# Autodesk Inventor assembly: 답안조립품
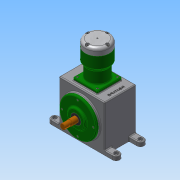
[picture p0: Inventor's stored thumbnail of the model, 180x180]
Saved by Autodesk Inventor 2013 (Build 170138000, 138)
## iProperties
Created: 2016-11
Part Number: 답안조립품
Document SubType Name: Assembly
Designer: Administrator
Author: Administrator
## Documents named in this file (16)
- C:\Users\Administrator\Desktop\361108V1018\답안조립품.iam
- C:\Users\Administrator\Desktop\361108V1018\본체.ipt
- C:\Users\Administrator\Desktop\361108V1018\메인크랭크축.ipt
- C:\Users\Administrator\Desktop\361108V1018\베어링 20 x 47 x 14.ipt
- C:\Users\Administrator\Desktop\361108V1018\베어링 NA 4902.ipt
- C:\Users\Administrator\Desktop\361108V1018\볼트 M4 x 8.ipt
- C:\Users\Administrator\Desktop\361108V1018\볼트 M5 x 20.ipt
- C:\Users\Administrator\Desktop\361108V1018\실린더.ipt
- C:\Users\Administrator\Desktop\361108V1018\실린더헤드.ipt
- C:\Users\Administrator\Desktop\361108V1018\앞커버.ipt
- C:\Users\Administrator\Desktop\361108V1018\오일 실 20 35 8.ipt
- C:\Users\Administrator\Desktop\361108V1018\커넥팅로드.ipt
- C:\Users\Administrator\Desktop\361108V1018\크랭크보조축.ipt
- C:\Users\Administrator\Desktop\361108V1018\피스톤.ipt
- C:\Users\Administrator\Desktop\361108V1018\피스톤핀.ipt
- C:\Users\Administrator\Desktop\361108V1018\가변스프링.ipt
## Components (15 placed, 5 different names)
1. 가변스프링:1
2. ISO 4762 M4 x 8:6
3. ISO 4762 M4 x 8:7
4. ISO 4762 M4 x 8:8
5. ISO 4762 M4 x 8:2
6. 피스톤:1
7. 피스톤핀:1
8. ISO 4762 M4 x 8:1
9. ISO 4762 M4 x 8:3
10. ISO 4762 M4 x 8:4
11. ISO 4762 M4 x 8:5
12. ISO 4762 M5 x 20:1
13. ISO 4762 M5 x 20:2
14. ISO 4762 M5 x 20:3
15. ISO 4762 M5 x 20:4
